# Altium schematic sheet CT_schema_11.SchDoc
size 389 x 385 mm
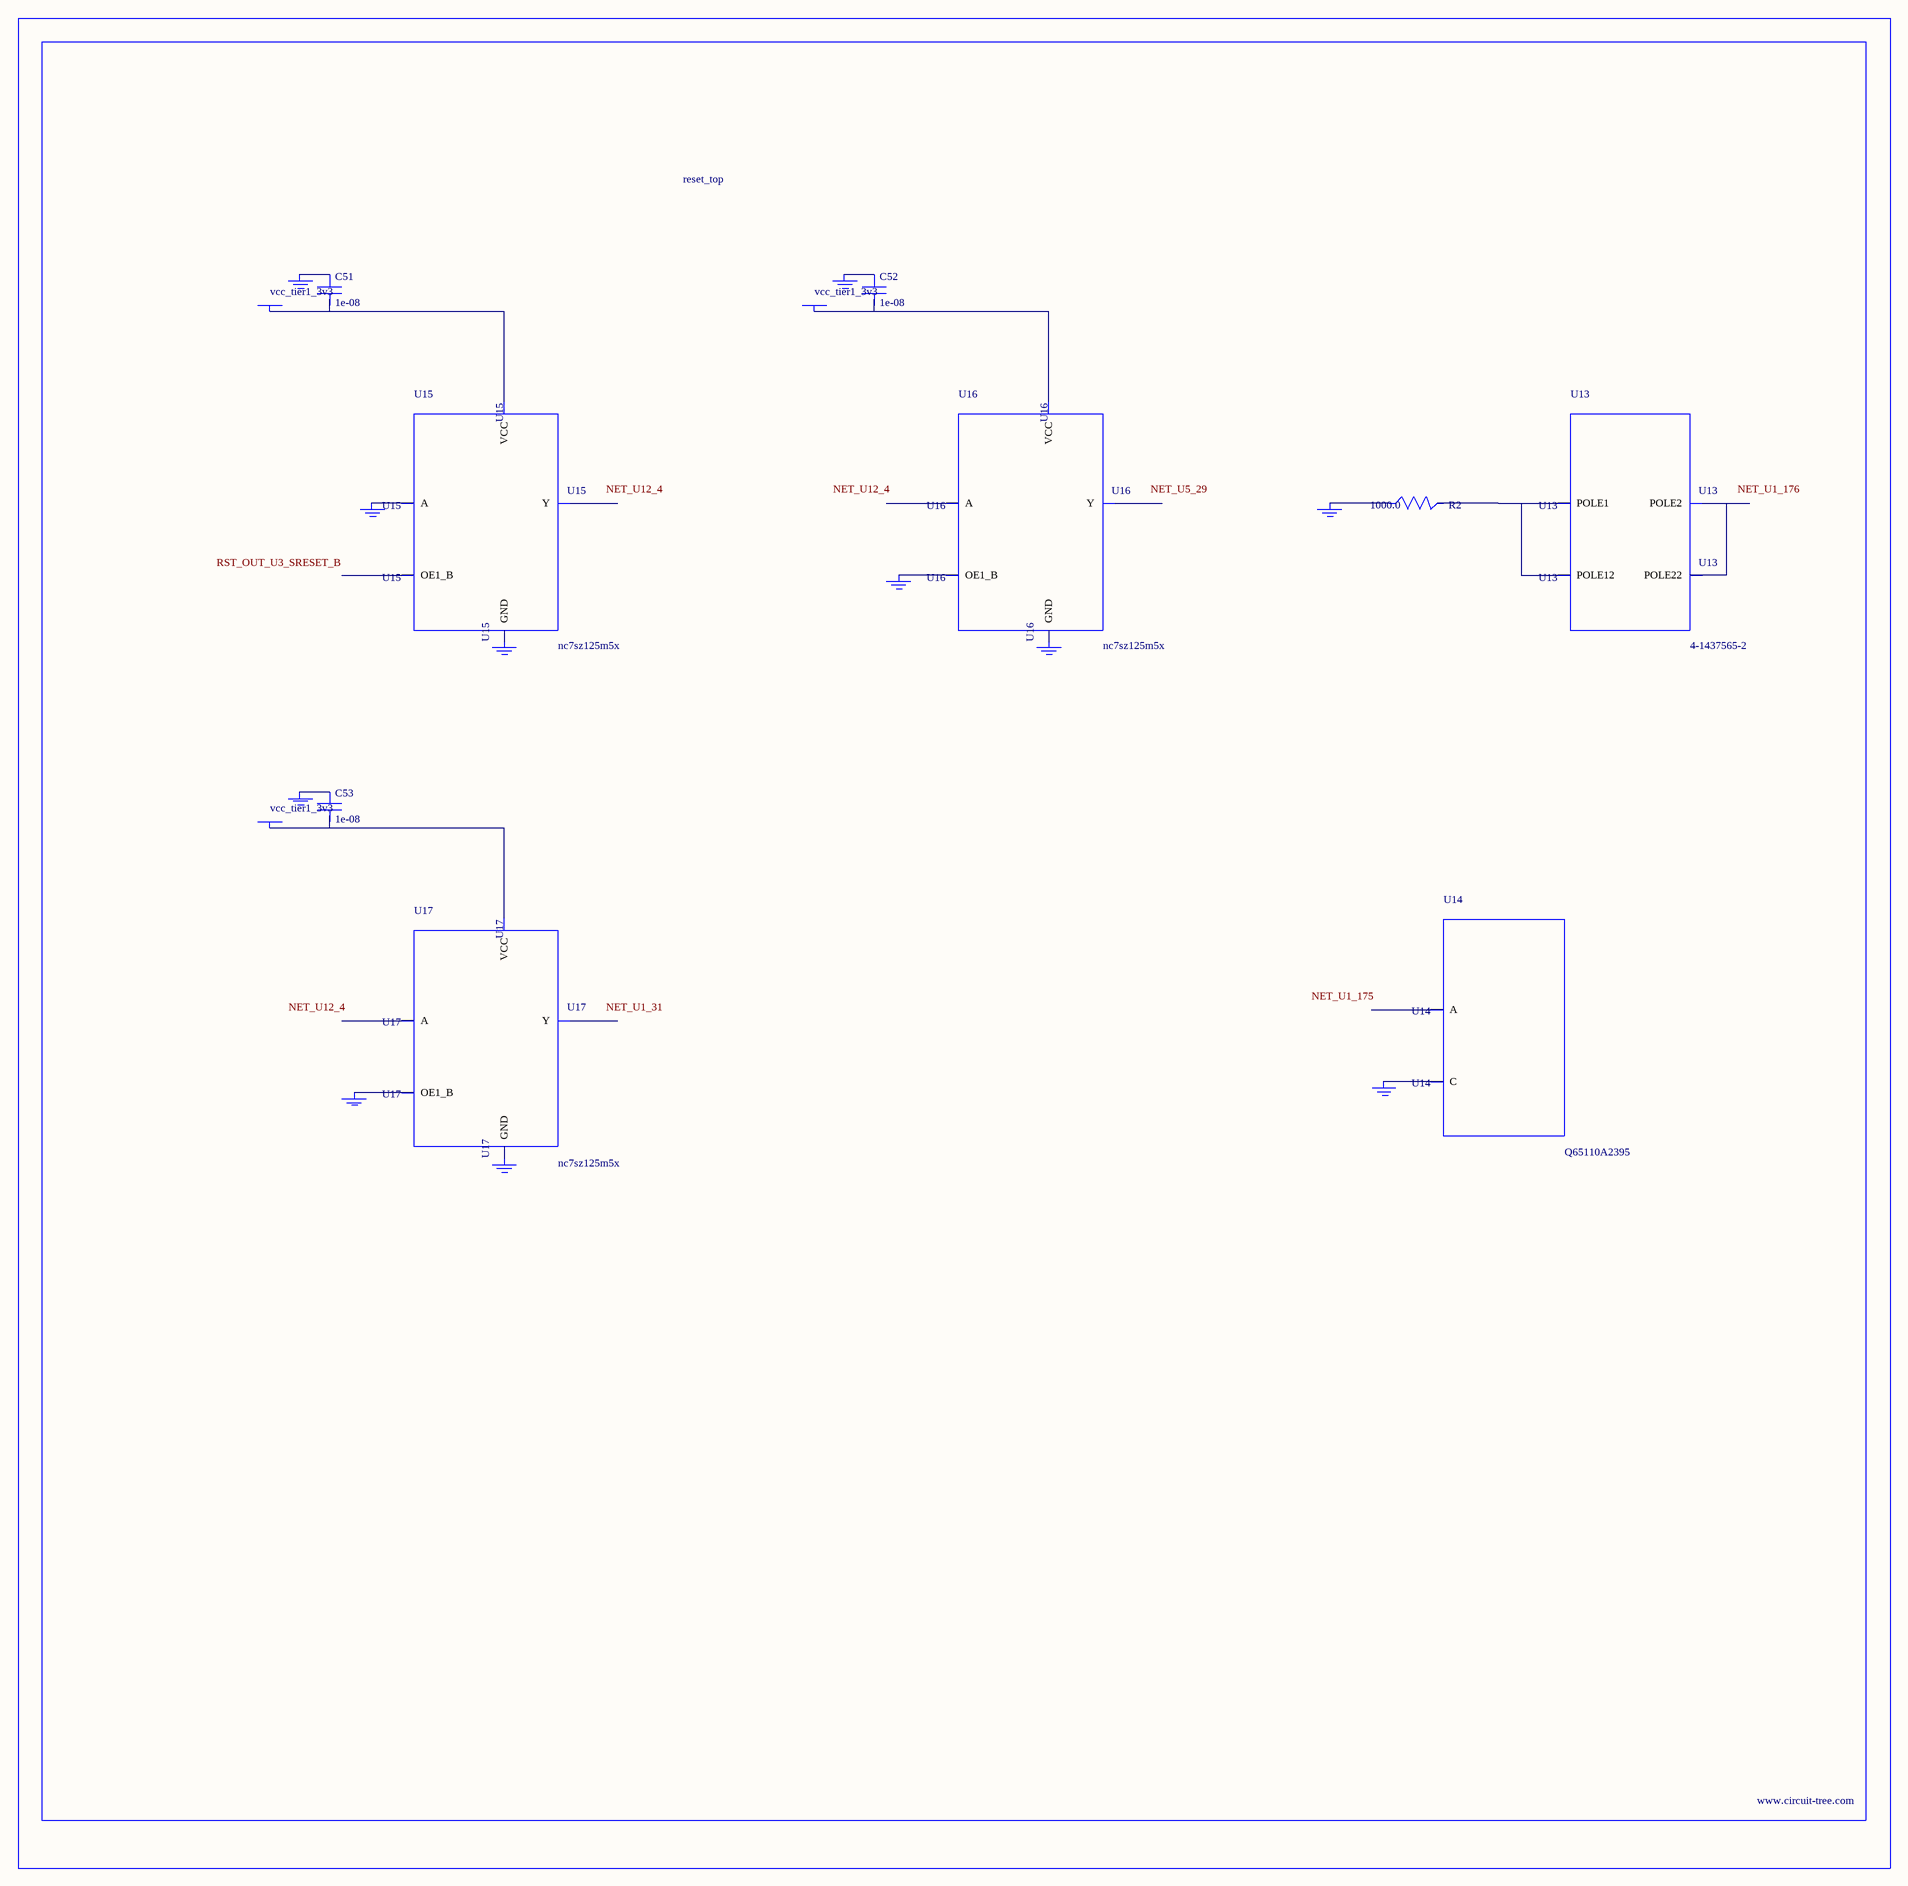
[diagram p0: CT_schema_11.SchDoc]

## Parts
BORDER10  (no value)
C51  1e-08  [C0402]
C52  1e-08  [C0402]
C53  1e-08  [C0402]
GND_INSTANCE_10_0  (no value)
GND_INSTANCE_10_1  (no value)
GND_INSTANCE_10_2  (no value)
GND_INSTANCE_10_3  (no value)
GND_INSTANCE_10_4  (no value)
GND_INSTANCE_10_5  (no value)
GND_INSTANCE_10_6  (no value)
GND_INSTANCE_10_7  (no value)
GND_INSTANCE_10_8  (no value)
GND_INSTANCE_10_9  (no value)
GND_INSTANCE_10_10  (no value)
POWER_INSTANCE_10_0  vcc_tier1_3v3
POWER_INSTANCE_10_1  vcc_tier1_3v3
POWER_INSTANCE_10_2  vcc_tier1_3v3
R2  1000.0  [R0603]
U13  4-1437565-2  [SW_4-1437565-2]
U14  Q65110A2395  [LGM67K-G1J2-24-Z]
U15  nc7sz125m5x  [NC7SZ125M5X]
U16  nc7sz125m5x  [NC7SZ125M5X]
U17  nc7sz125m5x  [NC7SZ125M5X]

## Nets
NetC51_1: C51.1 GND_INSTANCE_10_2.0(GND)
NetC51_2: C51.2 POWER_INSTANCE_10_0.0(PWR) U15.5(VCC)
NetC52_1: C52.1 GND_INSTANCE_10_5.0(GND)
NetC52_2: C52.2 POWER_INSTANCE_10_1.0(PWR) U16.5(VCC)
NetC53_1: C53.1 GND_INSTANCE_10_8.0(GND)
NetC53_2: C53.2 POWER_INSTANCE_10_2.0(PWR) U17.5(VCC)
NetGND_INSTANCE_10_0_0: GND_INSTANCE_10_0.0(GND) R2.1
NetGND_INSTANCE_10_1_0: GND_INSTANCE_10_1.0(GND) U14.C
NetGND_INSTANCE_10_3_0: GND_INSTANCE_10_3.0(GND) U15.2(A)
NetGND_INSTANCE_10_4_0: GND_INSTANCE_10_4.0(GND) U15.3(GND)
NetGND_INSTANCE_10_6_0: GND_INSTANCE_10_6.0(GND) U16.1(OE1_B)
NetGND_INSTANCE_10_7_0: GND_INSTANCE_10_7.0(GND) U16.3(GND)
NetGND_INSTANCE_10_9_0: GND_INSTANCE_10_9.0(GND) U17.1(OE1_B)
NetGND_INSTANCE_10_10_0: GND_INSTANCE_10_10.0(GND) U17.3(GND)
NetR2_2: R2.2 U13.1(POLE1) U13.2(POLE12)
NetU13_3: U13.3(POLE2) U13.4(POLE22)

Not connected (* = marked no-connect by the designer): U14 A; U15 1(OE1_B) 4(Y); U16 2(A) 4(Y); U17 2(A) 4(Y)

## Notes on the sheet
- Labels drawn without touching a wire or pin: NET_U1_31, NET_U1_175, NET_U1_176, NET_U5_29, NET_U12_4, RST_OUT_U3_SRESET_B

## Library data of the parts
BORDER10 = BORDER_PAGE10
C51-C53 = C0402C103K3RAC
GND_INSTANCE_10_0-GND_INSTANCE_10_10 = GND
POWER_INSTANCE_10_0-POWER_INSTANCE_10_2 = PWR
R2 = RC0603JR-071KL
